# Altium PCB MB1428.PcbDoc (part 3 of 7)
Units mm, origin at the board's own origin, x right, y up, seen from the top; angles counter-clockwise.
Board outline 55.88 x 152.4 mm, 4 copper layers (Top Layer, Signal Layer 1, Signal Layer 2, Bottom Layer), stack 1.614 mm thick; 396 components, 227 nets, 1346 pads, 1469 vias.
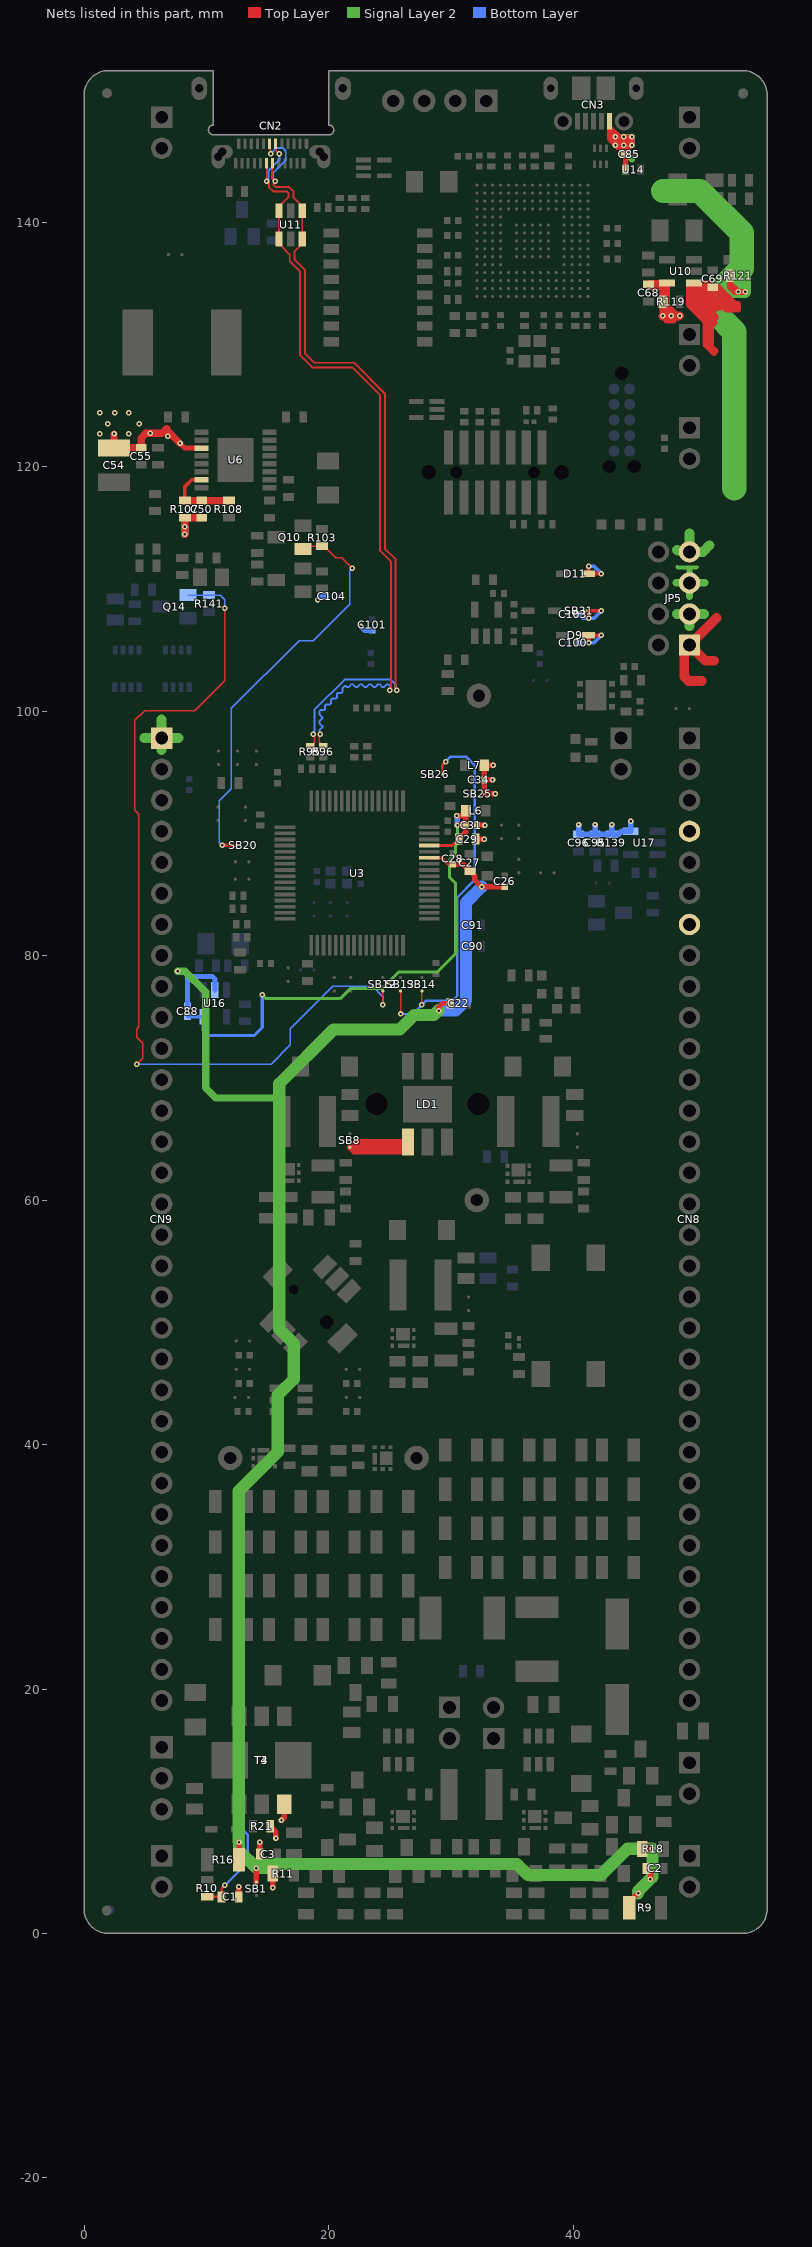
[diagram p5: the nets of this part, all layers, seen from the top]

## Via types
v1: diameter 0.45, hole 0.2, Top Layer to Bottom Layer, tented both sides, 1460 vias
v2: diameter 0.6, hole 0.2, Top Layer to Bottom Layer, tented both sides, 9 vias

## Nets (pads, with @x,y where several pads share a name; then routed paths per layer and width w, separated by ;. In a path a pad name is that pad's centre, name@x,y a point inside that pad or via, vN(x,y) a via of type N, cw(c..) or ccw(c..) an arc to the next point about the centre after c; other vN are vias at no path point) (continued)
5V_USB_CHGR: C68.2 C85.2 CN3.1 D11.1 JP5.7 R119.2 R121.2 U10.5 U14.1 | length 89.5
  Top Layer w0.3: v1(41.27,111.855) 41.27,111.255 v1(42.325,111.255)
  Top Layer w0.4: CN3.1@42.975,148.25 CN3.1@42.975,147.824 ; U14.1@44.3,144.3 44.3,145.4 C85.2@44.15,145.55 C85.2@44.15,145.625 ; 42.975,147.475 CN3.1@42.975,147.824 ; 42.975,147.475 43.2,147.25 ; 42.975,147.475 42.975,146.8 43.2,146.575 ; CN3.1@42.975,147.824 43.824,146.975 ; 43.2,146.575 43.2,147.25 ; 43.2,146.575 v1(43.475,146.3) ; 43.2,147.25 v1(43.475,146.975) ; v1(43.475,146.3) C85.2@44.15,145.625 ; v1(43.475,146.3) v1(44.15,146.975) ; v1(43.475,146.3) v1(44.15,146.3) ; v1(43.475,146.3) v1(43.475,146.975) ; v1(43.475,146.975) 43.824,146.975 ; 43.824,146.975 v1(44.15,146.975) ; C85.2@44.15,145.625 C85.2@44.15,145.638 ; C85.2@44.15,145.638 v1(44.15,146.3) ; C85.2@44.15,145.638 v1@44.812,146.3 ; v1(44.15,146.3) v1@44.812,146.3 ; v1(44.15,146.3) v1(44.15,146.975) ; v1(44.15,146.975) v1(44.825,146.3) ; v1(44.15,146.975) v1(44.825,146.975) v1(44.825,146.3) ; v1@44.812,146.3 v1(44.825,146.3)
  Top Layer w0.5: R121.2@52.83,135.625 52.83,134.98 ; v1(54.08,134.305) v1(53.505,134.305) ; v1(47.33,132.36) v1@48.025,132.36 ; v1(47.33,132.36) 47.33,132.302 47.657,131.975 48.209,131.975 48.419,132.185 48.55,132.185 ; v1(47.33,132.36) R119.2@47.33,133.055 ; R119.2@47.33,133.055 v1@48.025,132.36 ; R119.2@47.33,133.055 R119.2@47.33,133.5 R119.2@47.33,133.925 ; R119.2@47.33,133.925 47.33,134.65 ; R119.2@47.33,133.925 47.705,134.3 ; 47.33,134.65 46.455,134.65 C68.2@46.18,134.925 46.28,135.025 U10.5@47.705,135.025 ; 47.33,134.65 U10.5@47.705,135.025 ; 47.705,134.3 47.705,133.17 v1@48.515,132.36 ; 47.705,134.3 U10.5@47.705,135.025 ; v1@48.025,132.36 v1@48.515,132.36 ; v1@48.515,132.36 48.725,132.36 48.715,132.35 48.55,132.185 ; v1@48.515,132.36 48.525,132.35 48.55,132.325 48.55,132.185 ; 52.83,134.98 52.83,134.705 53.23,134.305 v1(53.505,134.305) ; 52.83,134.98 v1(53.505,134.305)
  Top Layer w0.7: v1@47.33,132.302 47.378,132.35 v1(48.025,132.35) 48.525,132.35 48.715,132.35 v1(48.725,132.35)
  Signal Layer 2 w0.5: 44.825,145.125 43.475,146.475 v1(43.475,146.975) ; v1(44.825,146.975) v1(44.15,146.975) ; v1(43.475,146.975) v1(44.15,146.975) ; v1(43.475,146.975) v1(44.15,146.3) v1(44.825,146.3) v1(44.15,146.975)
  Signal Layer 2 w0.8: 48.515,113.18 48.57,113.125 49.435,113.125 JP5.7@49.53,113.03 ; 49.53,114.555 JP5.7@49.53,113.03 ; 51.175,113.575 50.63,113.03 JP5.7@49.53,113.03
  Signal Layer 2 w1: 51.875,134.3 51.88,134.305 v1(53.505,134.305) v1(54.08,134.305) 54.08,135.945 53.8,136.225
  Signal Layer 2 w2: 47.4,142.55 50.375,142.55 53.8,139.125 53.8,136.225 51.88,134.305 ; 51.875,134.3 51.875,132.365 53.2,131.04 53.2,118.225
  Bottom Layer w0.3: v1(41.27,111.855) 41.725,111.855 v1(42.325,111.255)
  Bottom Layer w0.5: v1(47.33,132.36) 48.715,132.36 v1(48.725,132.35) ; v1(53.505,134.305) v1(54.08,134.305) ; v1(43.475,146.975) v1(43.475,146.3) v1(44.15,146.3) ; v1(43.475,146.975) v1(44.15,146.975) ; v1(43.475,146.975) v1(44.15,146.3) ; v1(44.15,146.3) v1(44.825,146.3) ; v1(44.15,146.975) v1(44.825,146.975) v1(44.825,146.3) ; v1(44.15,146.975) v1(44.825,146.3)
5V_USB_STLK: C69.2 JP5.1 U10.1 | length 46.6
  Top Layer w0.5: 50.063,133.013 49.905,133.17 U10.1@49.905,135.025 ; 50.17,134.538 50.17,134.23 ; 51.5,131.675 51.288,131.887 ; 51.525,129.312 50.855,129.983 50.855,131.871 49.512,133.214 49.512,134.938 49.6,135.025 U10.1@49.905,135.025 ; 51.563,131.787 51.288,132.062 ; 51.587,132.813 50.17,134.23 ; 51.637,129.475 51.288,129.825 51.288,131.887 ; 51.7,132.212 50.17,133.742 ; 52.038,133.025 51.905,133.025 50.695,134.235 ; 53.45,133.112 53.258,133.305 ; U10.1@49.905,135.025 U10.1@50.17,134.76 ; U10.1@49.905,135.025 U10.1@50.525,135.025 ; 50.17,133.18 51.288,132.062 ; 50.17,133.18 50.17,133.742 ; 50.17,133.18 50.17,133.005 51.288,131.887 ; 50.17,133.742 50.17,134.23 ; 50.17,134.23 U10.1@50.17,134.76 ; U10.1@50.17,134.76 50.695,134.235 ; U10.1@50.525,135.025 51.08,135.025 C69.2@51.43,134.675 ; U10.1@50.525,135.025 50.875,134.675 C69.2@51.43,134.675 ; 50.695,134.235 51.165,134.235 52.55,132.85 53.48,132.85 53.48,133.305 53.258,133.305 ; 51.288,131.887 51.288,132.062 ; C69.2@51.43,134.675 51.887,134.675 53.258,133.305 ; C69.2@51.43,134.675 52.8,133.305 53.258,133.305
  Top Layer w0.8: 50.538,102.475 49.45,102.475 49.1,102.825 49.1,104.98 JP5.1@49.53,105.41 ; 51.55,104.125 50.815,104.125 JP5.1@49.53,105.41 ; 51.75,107.63 JP5.1@49.53,105.41
5V_USBPD: C50.2 C54.2 C55.2 C103.2 C104.2 JP5.5 R107.2 SB31.1 U6.3 | length 24.6
  Top Layer w0.3: v1(41.27,107.605) 41.27,108.205 v1(42.325,108.205)
  Top Layer w0.4: v1(7.85,121.9) 8.225,121.525 U6.3@9.625,121.525
  Top Layer w0.6: v1(2.45,122.675) C54.2@2.45,121.525 2.475,121.55 C55.2@4.675,121.55 4.675,122.35 5.05,122.725 v1(5.425,122.725) 6.375,122.725 6.775,123.125 6.775,122.975 v1(7.85,121.9) ; v1(8.25,114.475) v1(8.25,115.075) R107.2@8.25,115.825 C50.2@9.625,115.825
  Signal Layer 2 w0.3: 48.525,111.8 48.57,111.755 50.058,111.755 50.078,111.775 50.175,111.775
  Signal Layer 2 w0.5: JP5.5@49.53,110.49 49.53,111.61 49.575,111.655
  Signal Layer 2 w0.6: 48.425,110.49 JP5.5@49.53,110.49 ; 49.53,109.375 JP5.5@49.53,110.49 ; 50.79,110.49 JP5.5@49.53,110.49
  Bottom Layer w0.3: C103.2@40.475,107.925 40.795,107.605 v1(41.27,107.605) ; v1@41.265,107.6 v1(41.27,107.605) ; v1(42.325,108.205) 41.725,107.605 v1@41.27,107.605
  Bottom Layer w0.4: v1(19.1,109.1) 19.4,109.4 C104.2@19.8,109.4
  Bottom Layer w0.45: v1@8.225,114.45 v1(8.25,114.475)
  Bottom Layer w0.6: v1(8.25,114.475) v1(8.25,115.075)
  other v1: 6.85,122.5 1.275,122.675 3.65,122.675 1.925,123.525 4.525,123.525 1.275,124.425 2.5,124.425 3.65,124.425
5V_USBPD_1A_PROTECT: Q10.1 R103.2 SB20.1 | length 34
  Top Layer w0.12: Q10.1@17.925,113.275 18.15,113.5 R103.2@19.475,113.5 19.655,113.5 20.592,112.563 21.087,112.563 v1(21.95,111.7)
  Top Layer w0.3: v1(11.3,89.025) SB20.1@12.475,89.025
  Bottom Layer w0.12: v1(11.3,89.025) 11.05,89.275 11.05,92.65 12.05,93.65 12.05,100.236 17.589,105.775 18.75,105.775 21.715,108.74 21.715,111.465 v1(21.95,111.7)
5V_VIN: C100.2 C101.2 CN9.1 D9.1 JP5.3 | length 13.4
  Top Layer w0.3: v1(41.27,105.605) D9.1@41.27,106.205 v1(42.325,106.205)
  Signal Layer 2 w0.8: 4.925,97.8 CN9.1@6.325,97.8 ; 6.325,96.825 CN9.1@6.325,97.8 ; 6.325,99.325 CN9.1@6.325,97.8 ; 7.725,97.8 CN9.1@6.325,97.8 ; 48.515,107.95 JP5.3@49.53,107.95 ; 49.53,106.94 JP5.3@49.53,107.95 ; 50.725,107.95 JP5.3@49.53,107.95
  Bottom Layer w0.25: C100.2@40.475,105.6 C100.2@40.48,105.605
  Bottom Layer w0.3: C100.2@40.48,105.605 v1(41.27,105.605) 41.725,105.605 v1(42.325,106.205)
  Bottom Layer w0.4: v1(22.625,106.925) 22.95,106.6 C101.2@23.575,106.6
AGND: C1.1 C2.1 C3.1 C22.1 C26.1 C27.1 C28.2 C29.1 C31.1 C34.2 C88.1 C90.1 C91.1 C95.1 C96.1 CN8.4 L7.2 R9.1 R11.1 R16.2 R18.1 R21.2 R139.1 SB1.1 SB25.2 T3.3 T4.3 U3.27 U16.2 U17.5 | length 192.4
  Top Layer w0.25: U3.27@28.239,88.004 29.264,88.004 29.789,87.479 C28.2@30.164,87.479
  Top Layer w0.4: v1(29,75.5) 29,75.775 29.325,76.1 C22.1@29.95,76.1
  Top Layer w0.45: C1.1@12.65,3 v1(12.65,3.825) ; R16.2@12.675,6.025 v1(12.675,7.45) ; SB1.1@14.1,4.2 v1(14.1,5.35) ; C3.1@14.375,6.5 v1(14.375,7.475) ; R21.2@15.225,8.775 15.7,8.3 v1(15.7,7.8) ; v1(15.425,3.75) R11.1@15.425,4.9 ; v1(16.15,9.275) 16.175,9.275 16.375,9.475 T3.3@16.375,10.575 ; C28.2@30.439,87.479 30.989,87.479 C27.1@31.564,86.904 31.964,86.504 31.964,86.191 v1(32.526,85.629) C26.1@34.414,85.629 ; C29.1@32.05,89.525 v1(32.75,89.525) ; C31.1@32.125,90.65 v1(32.8,90.65) ; v1(33.414,94.379) C34.2@32.739,94.379 ; v1(33.475,95.579) L7.2@32.739,95.579 C34.2@32.739,94.379 ; v1(33.625,93.229) SB25.2@32.739,93.229 C34.2@32.739,94.379 ; R9.1@44.6,2.1 44.6,2.575 v1(45.325,3.3) ; R18.1@45.675,6.925 v1(46.5,6.925) ; C2.1@46.025,5.325 46.35,5 46.35,4.45 v1(46.325,4.45)
  Signal Layer 2 w0.6: v1(7.65,78.725) 8.25,78.725 9.95,77.025 9.95,69.175 10.775,68.35 15.975,68.35
  Signal Layer 2 w1: v1@29,75.525 28.609,75.134 27.004,75.134 25.82,73.95 20.4,73.95 15.975,69.525 15.975,68.35 15.975,49.45 17.15,48.275 17.15,45.35 15.85,44.05 15.85,39.4 12.65,36.2 12.675,36.175 12.65,36.15 12.65,7.475 v1(12.675,7.45) 12.675,6.775 v1(14.1,5.35) ; v1(45.325,3.3) 45.325,3.45 v1(46.325,4.45) 46.5,4.625 v1(46.5,6.925) 44.45,6.925 42.3,4.775 36.325,4.775 35.405,5.695 15.945,5.695 ; v1(14.1,5.35) 14.445,5.695 15.945,5.695 ; v1(14.1,5.35) 15.6,5.35 15.945,5.695
  Bottom Layer w0.2: C90.1@31.1,80.75 31.125,80.775 C90.1@31.125,80.825
  Bottom Layer w0.4: v1(7.65,78.725) 8.1,78.725 8.55,78.275 ; C88.1@8.475,75.9 8.475,78.2 8.55,78.275 ; U16.2@10.7,77.2 10.7,78.1 10.525,78.275 8.55,78.275
  Bottom Layer w0.45: v1(40.45,90.725) C96.1@40.45,89.925 C95.1@41.8,89.925 ; v1(41.8,90.725) C95.1@41.8,89.925 ; v1(43.175,90.725) R139.1@43.175,89.925 ; v1(44.725,90.975) U17.5@44.725,90.175 43.975,90.175 43.725,89.925 R139.1@43.175,89.925 ; C95.1@41.8,89.925 R139.1@43.175,89.925
  Bottom Layer w1: v1(29,75.5) 30.4,75.5 31.25,76.35 31.25,84.353 v1(32.526,85.629)
AVDD: C29.2 C31.2 C88.2 CN8.7 L6.2 U3.29 U16.5 | length 46.2
  Top Layer w0.25: U3.29@28.239,89.004 30.129,89.004 C29.2@30.65,89.525
  Top Layer w0.4: L6.2@31.225,91.425 31.225,91.825 L6.2@31.25,91.85
  Top Layer w0.45: v1(30.5,91.425) 31.225,91.425 31.214,91.414 C31.2@31.214,90.65 ; v1(30.55,90.65) C31.2@31.214,90.65 ; C29.2@30.65,89.525 31.214,90.089 C31.2@31.214,90.65 ; C31.2@31.225,90.65 C31.2@31.214,90.65
  Signal Layer 2 w0.25: v1(14.575,76.8) 14.9,76.475 20.95,76.475 21.775,77.3 24.375,77.3 25.725,78.65 28.875,78.65 30.4,80.175 30.4,85.9 29.9,86.4 29.9,87.8 30.4,88.3 30.4,89 30.55,89.15 v1(30.55,90.65)
  Bottom Layer w0.25: C88.2@8.475,75 U16.5@9.75,75 9.75,73.875 10.175,73.45 13.9,73.45 14.575,74.125 v1(14.575,76.8)
  Bottom Layer w0.45: v1(30.5,91.425) 30.55,91.375 v1(30.55,90.65)
BLUE_LED_K: LD1.1 SB8.2 | length 15.3
  Top Layer w0.5: 21.925,64.325 SB8.2@21.75,64.325 22.1,63.975 26.25,63.975 26.6,64.325 LD1.1@26.075,64.325 ; 21.925,64.325 22.35,64.75 LD1.1@26.5,64.75 LD1.1@26.075,64.325 ; 21.925,64.325 LD1.1@26.075,64.325
BUCKBOOST_I_IN_AVG: C1.2 R10.1 SB13.1 SB14.1 SB26.2 | length 116.3
  Top Layer w0.12: SB13.1@25.889,77.104 25.889,75.236 v1(25.9,75.225) ; v1(27.639,75.979) SB14.1@27.639,77.104
  Top Layer w0.2: R10.1@10.075,3 C1.2@11.25,3 11.25,3.675 v1(11.525,3.95) ; SB26.2@29.3,94.825 29.3,95.6 v1(29.575,95.875)
  Bottom Layer w0.2: v1(11.525,3.95) 13.4,5.825 13.4,8.05 12.65,8.8 12.65,36.3 15.875,39.525 15.875,44.125 17.125,45.375 17.125,48.35 15.95,49.525 15.95,69.525 20.35,73.925 25.585,73.925 26.885,75.225 ; v1@25.889,75.225 v1(25.9,75.225) 26.885,75.225 ; v1(29.575,95.875) 29.975,96.275 31.258,96.275 31.95,95.583 31.95,86.175 30.53,84.755 30.53,76.705 30.125,76.3 27.96,76.3 v1(27.639,75.979) 26.885,75.225
BUCKBOOST_USBPD_EN: Q14.1 R141.2 SB12.1 | length 72.9
  Top Layer w0.12: v1(4.327,71.125) 4.818,71.616 4.818,72.812 4.318,73.312 4.318,73.992 4.489,74.163 4.489,91.561 4.157,91.893 4.157,99.24 4.963,100.046 9.071,100.046 11.525,102.5 v1(11.525,108.425) ; v1(24.439,75.979) SB12.1@24.439,77.104
  Bottom Layer w0.12: v1(4.327,71.125) 15.3,71.125 16.875,72.7 16.875,74.025 20.325,77.475 23.6,77.475 24.439,76.636 v1(24.439,75.979) ; Q14.1@8.5,109.5 R141.2@10.225,109.5 11.15,109.5 11.525,109.125 v1(11.525,108.425)
D_N: CN2.A7 CN2.B7 R96.1 U11.3 U11.4 | length 66.5
  Top Layer w0.16: CN2.A7@14.925,144.82 14.982,144.763 14.982,143.407 v1(14.925,143.35) 15.125,143.15 15.125,142.875 15.5,142.5 16.604,142.5 16.739,142.365 16.739,142.097 16,141.358 U11.3@16,141.275 ; CN2.B7@15.675,146.42 15.675,145.9 v1(15.975,145.6) ; U11.3@15.95,141.275 U11.3@15.95,140.925 U11.4@15.95,138.625 15.95,138.225 16.825,137.35 16.825,136.8 17.675,135.95 17.675,129.104 18.665,128.114 21.936,128.114 24.225,125.825 24.225,113.125 25.1,112.25 25.1,101.792 v1(25.008,101.7) ; v1(19.331,98.104) 19.239,98.012 19.239,97.454 R96.1@19.564,97.129
  Bottom Layer w0.16: v1(14.925,143.35) 15.089,143.514 15.089,144.21 15.975,145.096 v1(15.975,145.6) ; v1(19.331,98.104) 19.25,98.185 19.25,98.428 19.5,98.678 19.5,98.775 19.25,99.025 19.25,99.153 19.5,99.403 19.5,99.5 19.25,99.75 19.25,99.978 19.347,100.075 19.65,100.075 19.725,100.15 19.725,100.453 19.728,100.453 19.825,100.55 20.125,100.55 20.203,100.628 20.203,100.928 20.3,101.025 20.6,101.025 20.678,101.103 20.678,101.403 20.775,101.5 21.053,101.5 21.153,101.6 21.153,101.878 21.338,102.063 21.412,102.063 21.511,101.964 21.636,101.964 21.872,102.2 22,102.2 22.236,101.964 22.361,101.964 22.597,102.2 22.725,102.2 22.961,101.964 23.086,101.964 23.322,102.2 23.45,102.2 23.686,101.964 23.811,101.964 24.047,102.2 24.175,102.2 24.411,101.964 24.536,101.964 24.772,102.2 24.904,102.2 25.1,102.004 25.1,101.792 v1(25.008,101.7)
D_P: CN2.A6 CN2.B6 R95.1 U11.1 U11.6 | length 67.5
  Top Layer w0.16: CN2.B6@15.175,146.42 15.175,146.019 15.244,145.95 15.244,145.631 v1(15.275,145.6) ; CN2.A6@15.425,144.82 15.368,144.763 15.368,143.607 v1(15.625,143.35) 15.625,143.264 15.511,143.15 15.511,143.035 15.66,142.886 16.764,142.886 17.125,142.525 17.125,142.033 17.85,141.308 U11.1@17.85,140.925 U11.6@17.85,138.625 17.85,138.225 17.211,137.586 17.211,136.96 18.061,136.11 18.061,129.264 18.825,128.5 22.096,128.5 24.611,125.985 24.611,113.285 25.486,112.41 25.486,101.792 v1(25.578,101.7) ; R95.1@18.514,97.129 18.853,97.468 18.853,98.012 v1(18.761,98.104)
  Bottom Layer w0.16: v1(15.275,145.6) 15.75,146.075 16.25,146.075 16.5,145.825 16.5,145.075 15.475,144.05 15.475,143.5 v1(15.625,143.35) ; v1(18.761,98.104) 18.864,98.207 18.864,100.138 21.312,102.586 25.071,102.586 25.486,102.171 25.486,101.792 v1(25.578,101.7)
FB: C50.1 R107.1 R108.2 U6.7 | length 6.4
  Top Layer w0.3: R107.1@8.25,117.225 8.25,118.375 8.8,118.925 U6.7@9.625,118.925
  Top Layer w0.6: R107.1@8.25,117.225 C50.1@9.625,117.225 10.425,117.225 R108.2@11.85,117.225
